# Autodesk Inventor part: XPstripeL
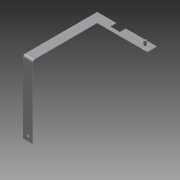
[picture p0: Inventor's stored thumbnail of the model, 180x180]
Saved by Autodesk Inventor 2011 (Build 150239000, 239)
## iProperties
Created: 2014-11
Part Number: XPstripeL
Document SubType Name: Modeling
Designer: Evgeny
Density: 1 g/cm^3
Author: Evgeny
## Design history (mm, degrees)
sketch "Эскиз1"
  geometry: L1 (17, 28)-(17, 32); L2 (-4, 28)-(-4, 1); L3 (-4, 1)-(-8, 1); L4 (-8, 32)-(-8, 1); L5 (0, 29.5)-(4, 29.5); L6 (0, 29.5)-(0, 32); L7 (4, 29.5)-(4, 32); L8 (17, 32)-(4, 32); L9 (0, 32)-(-8, 32); L10 (-4, 28)-(17, 28); C1 r 0.5 at (14, 30); 1 further point
  constraints: 20 end point, 3 perpendicular, 2 horizontal, 2 parallel, 1 centre point
  dimensions: "d1" = 25 distance between parallel lines of L4 L1; "d2" = 4 distance between parallel lines of L2 L4; "d3" = 1 diameter of C1; "d4" = 3 distance from line of L1 C1.centre; "d26" = 4 distance between parallel lines of L10 L8; "d27" = 13 distance between parallel lines of L7 L1; "d28" = 4 distance between parallel lines of L6 L7; "d29" = 1.5 distance between parallel lines of L10 L5
extrude "Выдавливание1" new body sketch "Эскиз1" distance "d10" = 0.25; taper "d11" = 0 deg
sketch "Эскиз3"
  geometry: L1 (8, 1)-(8, 32) reference; L2 (4, 1)-(8, 1); L3 (8, 1)-(8, 1.25); L4 (8, 1.25)-(4, 1.25); L5 (4, 1.25)-(4, 1); 1 further point
  constraints: 8 end point, 2 parallel, 1 horizontal, 1 perpendicular, 1 point on line
  dimensions: "d30" = 0.25 distance between parallel lines of L4 L2
extrude "Выдавливание3" join sketch "Эскиз3" distance "d31" = 30; taper "d32" = 0 deg
fillet "Сопряжение3" dims "d33" = 0.75
fillet "Сопряжение4" dims "d34" = 1
hole "Отверстие2" diameter "d37" = 1; stored, may be unused: countersink angle "d41" = 90 deg, drill point angle "d43" = 118 deg; dims "d35" = 2, "d36" = 2, "d38" = 6, "d39" = 4, "d40" = 2, "d42" = 1
extrude "Выдавливание4" join sketch "Эскиз1" distance "d44" = 2; taper "d45" = 0 deg
node "Твердое тело1"
other parameters: "d0" = 31, "d5" = 4, "d6" = 2, "d9" = 1.5
